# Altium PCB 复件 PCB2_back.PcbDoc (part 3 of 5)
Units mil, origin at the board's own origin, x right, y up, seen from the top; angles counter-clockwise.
Board outline 6299 x 3937 mil, 4 copper layers (TopLayer, GROUND, VCC, BottomLayer); 290 components, 470 nets, 2252 pads, 827 vias.
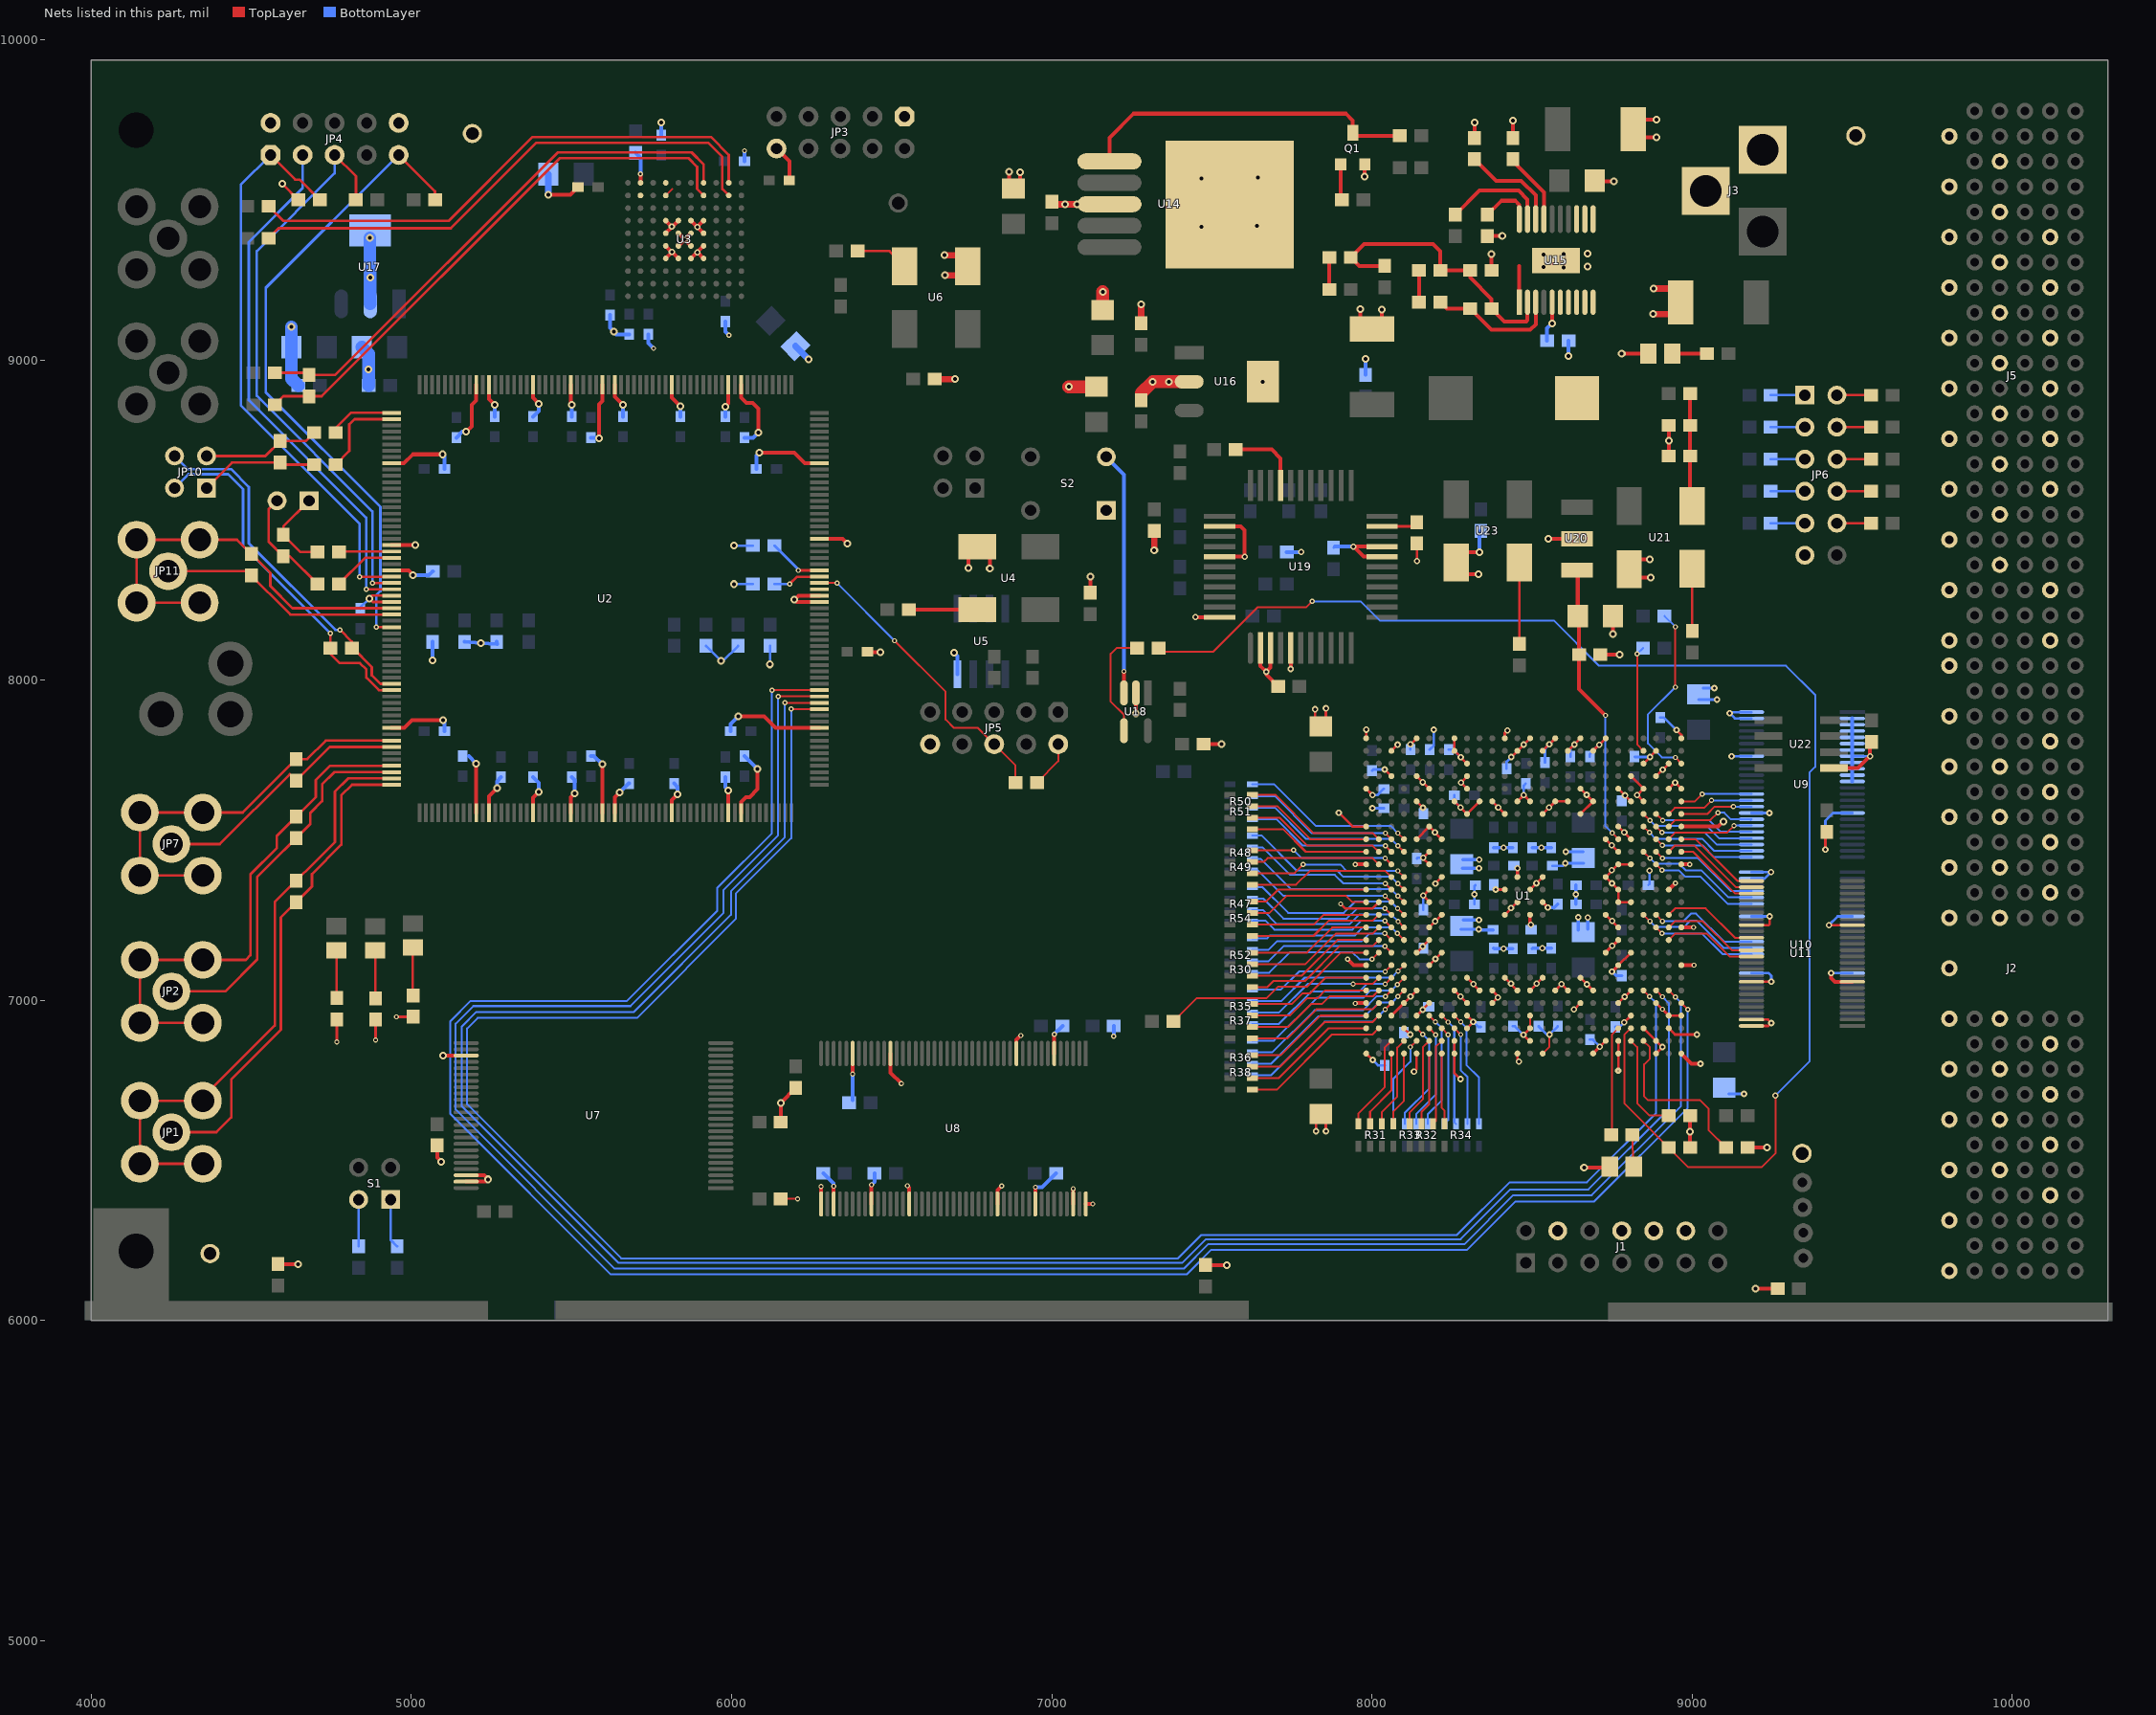
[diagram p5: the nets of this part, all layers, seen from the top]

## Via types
v1: diameter 16, hole 8, TopLayer to BottomLayer, 408 vias
v2: diameter 20, hole 10, TopLayer to BottomLayer, 220 vias
v3: diameter 24, hole 12, TopLayer to BottomLayer, 196 vias
v4: diameter 56.69, hole 56.69, TopLayer to BottomLayer, 2 vias
v5: diameter 20, hole 0, TopLayer to BottomLayer, 1 vias

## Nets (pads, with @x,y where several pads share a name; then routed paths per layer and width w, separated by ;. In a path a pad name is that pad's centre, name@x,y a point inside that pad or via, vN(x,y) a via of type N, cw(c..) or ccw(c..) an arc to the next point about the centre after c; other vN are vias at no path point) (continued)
GND: C5.1 C6.1 C7.1 C8.1 C9.1 C10.1 C11.1 C14.2 C15.2 C16.1 C17.1 C18.1 C19.1 C20.1 C21.1 C22.1 C23.1 C24.1 C25.1 C26.1 C27.2 C37.2 C38.2 C39.2 C40.2 C41.2 C42.2 C43.2 C44.2 C45.2 C46.2 C47.2 C48.2 C49.2 C50.2 C51.2 C52.2 C53.2 C54.1 C55.2 C56.2 C57.2 C58.2 C59.2 C60.2 C63.1 C64.1 C65.2 C66.2 C67.2 C68.2 C69.2 C70.2 C71.2 C72.2 C73.2 C74.2 C75.2 C76.2 C77.2 C78.1 C79.2 C80.2 C81.2 C82.2 C83.2 C84.2 C85.2 C86.2 C87.2 C90.1 C95.1 C96.1 C97.2 C98.2 C99.2 C100.2 C101.2 C103.2 C104.2 C105.2 C106.2 C107.2 C108.2 C109.2 C110.2 C111.2 C112.2 C114.2 C115.2 C116.2 C117.2 C119.2 C120.2 C121.2 C123.2 C124.2 C125.1 C126.1 C127.1 C128.1 C129.1 C130.1 C131.1 C132.1 C133.1 C134.2 C135.2 C136.2 C137.2 C138.2 C139.2 C140.2 C141.2 C142.2 C143.2 C144.2 C145.2 C146.2 C147.2 C148.2 C149.2 C150.2 C151.2 C152.2 C154.1 C156.1 C158.1 C160.1 C161.1 C162.1 C163.1 C164.2 C165.1 C166.1 DS6.2 DS9.2 FB5.2 FB6.2 FB7.2 FB8.2 J1.4 J1.8 J1.10 J1.12 J2.B4 J2.B6 J2.B8 J2.B10 J2.B16 J2.B18 J2.B20 J2.B22 J2.D5 J2.D7 J2.D9 J2.D11 J2.D15 J2.D17 J2.D19 J2.D21 J2.F1 J2.F3 J2.F5 J2.F7 J2.F9 J2.F11 J2.F13 J2.F15 J2.F17 J2.F19 J2.F21 J2.F23 J2.F25 J3.2 J3.3 J5.B1 J5.B3 J5.B7 J5.B9 J5.B11 J5.B13 J5.B15 J5.B17 J5.D4 J5.D6 J5.D8 J5.D10 J5.D12 J5.D14 J5.D16 J5.D18 J5.D20 J5.F1 J5.F3 J5.F5 J5.F7 J5.F9 J5.F11 J5.F13 J5.F15 J5.F17 J5.F19 J5.F21 JP3.1 JP3.10 JP4.2 JP4.10 JP5.2 JP5.10 JP6.11 pad.5 pad.6 pad.7 pad.8 Q1.3 R15.2 R17.1 R18.2 R19.2 R22.1 R23.1 R28.1 R39.2 R59.1 R65.1 R67.1 R79.1 R83.1 R84.1 S2.1 U1.A1 U1.A3 U1.A6 U1.A8 U1.A12 U1.A14 U1.A19 U1.A22 U1.A26 U1.AA4 U1.AA5 U1.AA8 U1.AA10 U1.AA11 U1.AA13 U1.AA14 U1.AA16 U1.AA17 U1.AA19 U1.AA22 U1.AB1 U1.AB2 U1.AB4 U1.AB6 U1.AB9 U1.AB18 U1.AB21 U1.AB26 U1.AC3 U1.AC5 U1.AC18 U1.AC22 U1.AC24 U1.AD2 U1.AD4 U1.AD18 U1.AE3 U1.AE8 U1.AE10 U1.AE12 U1.AE14 U1.AE19 U1.AE24 U1.AF1 U1.AF7 U1.AF9 U1.AF11 U1.AF13 U1.AF15 U1.AF19 U1.AF22 U1.AF26 U1.B3 U1.B6 U1.B7 U1.B13 U1.B19 U1.C2 U1.C4 U1.C13 U1.C18 U1.C23 U1.D1 U1.D2 U1.D5 U1.D13 U1.D18 U1.D22 U1.D24 U1.E3 U1.E6 U1.E9 U1.E16 U1.E18 U1.E21 U1.E23 U1.E26 U1.F5 U1.F8 U1.F10 U1.F11 U1.F13 U1.F14 U1.F16 U1.F17 U1.F19 U1.F22 U1.G9 U1.G12 U1.G15 U1.G18 U1.H1 U1.H6 U1.H21 U1.H26 U1.J5 U1.J7 U1.J20 U1.J22 U1.K6 U1.K21 U1.L1 U1.L6 U1.L21 U1.M7 U1.M13 U1.M15 U1.M20 U1.N5 U1.N6 U1.N12 U1.N14 U1.N21 U1.N25 U1.P2 U1.P6 U1.P13 U1.P15 U1.P21 U1.R7 U1.R12 U1.R14 U1.R20 U1.T1 U1.T5 U1.T6 U1.T21 U1.T26 U1.U6 U1.U21 U1.V5 U1.V7 U1.V20 U1.V22 U1.W1 U1.W6 U1.W21 U1.W26 U1.Y9 U1.Y12 U1.Y15 U1.Y18 U2.10 U2.30 U2.31 U2.40 U2.52 U2.69 U2.71 U2.80 U2.89 U2.91 U2.96 U2.102 U2.109 U2.111 U2.129 U2.142 U2.150 U2.151 U2.171 U2.190 U2.192 U2.199 U2.205 U2.210 U2.212 U2.221 U2.230 U2.232 U3.D4 U3.D5 U3.D6 U3.D7 U3.E4 U3.E5 U3.E6 U3.E7 U3.F4 U3.F5 U3.F6 U3.F7 U3.G4 U3.G5 U3.G6 U3.G7 U4.2 U5.4 U6.2 U7.27 U7.46 U7.47 U8.6 U8.12 U8.32 U8.38 U8.44 U8.46 U8.52 U8.58 U8.72 U8.78 U8.84 U8.86 U9.2 U9.3 U9.4 U9.5 U9.6 U9.7 U9.8 U9.9 U9.10 U9.11 U9.12 U9.17 U9.32 U9.41 U9.47 U9.48 U10.8 U10.17 U10.32 U10.41 U10.47 U10.48 U11.8 U11.17 U11.32 U11.41 U11.47 U11.48 U14.3 U15.1 U15.11 U15.12 U15.13 U16.2 U16.4 U17.2 U17.4 U18.2 U19.2 U19.3 U19.5 U19.18 U19.19 U19.35 U19.38 U19.44 U20.2 U21.2 U22.5 U23.2 | length 21482.2
  TopLayer w6: R59.1@6153.46,6380 v1(6206,6380) ; R28.1@6953.46,7680 7020,7746.54 JP5.2@7020,7800 ; U1.C13@8493.56,6912.74 U1.D13@8493.56,6952.11 ; U1.A12@8532.93,6834 8553.99,6855.06 v2(8553.99,6893)
  TopLayer w8: v3(4596.54,9550) R17.1@4646.54,9500 ; v1(4767,6870) R19.2@4767,6940.54 ; v1(4888,6876) R18.2@4888,6939.54 ; U2.151@4937.69,8244.16 4878.84,8244.16 v3(4868,8255) 4876.84,8263.84 U2.150@4937.69,8263.84 ; v1(4952.54,6948.54) R15.2@5005,6948.54 ; C147.2@7822,7855 v2(7822,7909) ; v2(7825,6591) C150.2@7825,6639 ; v2(7856,6591) C150.2@7856,6644 ; C147.2@7856,7851 v2(7856,7912) ; v2(7896,7586) 7939.34,7542.66 U1.W26@7981.75,7542.66 ; v1(7902,7301) 7916,7287 8001.68,7287 U1.N25@8021.12,7306.44 ; U1.A26@7981.75,6834 v2(8002,6813.75) ; U1.AB26@7981.75,7660.77 v2(8001.52,7641) ; U1.AF26@7981.75,7818.25 v2(7981.75,7845.25) ; v2(8039.63,7721) U1.AC24@8060.49,7700.14 ; U1.D24@8060.49,6952.11 U1.F22@8139.23,7030.85 ; U1.AE24@8060.49,7778.88 v2(8080,7798.39) ; U1.C23@8099.86,6912.74 v2(8119.6,6893) ; v2(8120,7799.02) U1.AF22@8139.23,7818.25 ; v2(8131,6777) 8139.23,6785.23 U1.A22@8139.23,6834 ; U1.D22@8139.23,6952.11 U1.E21@8178.6,6991.48 ; U1.J22@8139.23,7148.96 U1.K21@8178.6,7188.33 ; U1.V22@8139.23,7503.29 U1.W21@8178.6,7542.66 U1.V20@8217.97,7503.29 ; U1.AA22@8139.23,7621.4 v2(8159,7601.63) ; U1.AC22@8139.23,7700.14 U1.AB21@8178.6,7660.77 ; v2(8140,8372) R39.2@8140,8426.54 ; U1.H21@8178.6,7109.59 U1.J20@8217.97,7148.96 ; U1.L21@8178.6,7227.7 U1.M20@8217.97,7267.07 ; U1.N21@8178.6,7306.44 8178.6,7308.4 v2(8160,7327) 8178.6,7345.6 U1.P21@8178.6,7345.81 ; U1.T21@8178.6,7424.55 8159.68,7443.47 v2(8159.68,7445) U1.U21@8178.6,7463.92 ; v2(8197.79,7365) U1.R20@8217.97,7385.18 ; U1.B19@8257.34,6873.37 8257.34,6772.66 v2(8276,6754) ; U1.F19@8257.34,7030.85 U1.E18@8296.71,6991.48 ; U1.AA19@8257.34,7621.4 U1.Y18@8296.71,7582.03 U1.AA17@8336.08,7621.4 ; U1.AF19@8257.34,7818.25 U1.AE19@8257.34,7778.88 U1.AD18@8296.71,7739.51 ; U1.C18@8296.71,6912.74 8316,6932.03 v2(8316,6932.82) U1.D18@8296.71,6952.11 ; U1.G18@8296.71,7070.22 U1.F17@8336.08,7030.85 ; U1.AB18@8296.71,7660.77 8278,7679.48 v2(8278,7680) 8296.71,7698.71 U1.AC18@8296.71,7700.14 ; U1.E16@8375.45,6991.48 v2(8393,7009.03) 8393,7013.3 U1.F16@8375.45,7030.85 ; U1.AA16@8375.45,7621.4 U1.Y15@8414.82,7582.03 ; U1.G15@8414.82,7070.22 U1.F14@8454.19,7030.85 ; U1.M15@8414.82,7267.07 U1.N14@8454.19,7306.44 ; U1.AF15@8414.82,7818.25 8414.82,7834.82 v2(8423,7843) ; v2(8435,7759.69) v2(8473.88,7798.58) U1.AF13@8493.56,7818.25 ; U1.A14@8454.19,6834 8454.19,6813.81 v2(8459,6809) ; U1.AA14@8454.19,7621.4 v2(8473.79,7641) 8473.96,7641 U1.AA13@8493.56,7621.4 ; U1.B13@8493.56,6873.37 8491.45,6873.37 v2(8472.82,6892) U1.C13@8493.56,6912.74 ; U1.F13@8493.56,7030.85 U1.G12@8532.93,7070.22 ; U1.P13@8493.56,7345.81 U1.R12@8532.93,7385.18 ; U1.Y12@8532.93,7582.03 U1.AA11@8572.3,7621.4 U1.AA10@8611.67,7621.4 ; U1.AE12@8532.93,7778.88 U1.AF11@8572.3,7818.25 ; U1.F11@8572.3,7030.85 8591.52,7050.07 v2(8591.52,7051) U1.F10@8611.67,7030.85 ; U1.AE10@8611.67,7778.88 U1.AF9@8651.04,7818.25 ; v2(8631,6971.44) U1.E9@8651.04,6991.48 ; U1.G9@8651.04,7070.22 U1.F8@8690.41,7030.85 ; U1.Y9@8651.04,7582.03 U1.AA8@8690.41,7621.4 U1.AB9@8651.04,7660.77 ; U1.A8@8690.41,6834 U1.B7@8729.78,6873.37 ; U1.AE8@8690.41,7778.88 U1.AF7@8729.78,7818.25 ; U1.M7@8729.78,7267.07 U1.L6@8769.15,7227.7 ; U1.V7@8729.78,7503.29 U1.U6@8769.15,7463.92 ; v5(8769,6780) 8769.15,6780.15 U1.B6@8769.15,6873.37 ; U1.E6@8769.15,6991.48 U1.F5@8808.52,7030.85 ; U1.H6@8769.15,7109.59 U1.J5@8808.52,7148.96 ; U1.W6@8769.15,7542.66 U1.V5@8808.52,7503.29 ; U1.AB6@8769.15,7660.77 U1.AA5@8808.52,7621.4 ; v2(8787.41,6931) U1.D5@8808.52,6952.11 ; U1.N5@8808.52,7306.44 U1.N6@8769.15,7306.44 U1.P6@8769.15,7345.81 U1.R7@8729.78,7385.18 U1.T6@8769.15,7424.55 U1.T5@8808.52,7424.55 ; U1.AC5@8808.52,7700.14 U1.AB4@8847.89,7660.77 v2(8828.12,7641) 8828,7641 8847.6,7621.4 U1.AA4@8847.89,7621.4 ; U1.C4@8847.89,6912.74 8906.63,6854 v2(8907.26,6854) U1.A3@8887.26,6834 ; U1.AD4@8847.89,7739.51 U1.AE3@8887.26,7778.88 ; U1.E3@8887.26,6991.48 U1.D2@8926.63,6952.11 U1.D1@8966,6952.11 ; U1.AC3@8887.26,7700.14 U1.AD2@8926.63,7739.51 ; U1.C2@8926.63,6912.74 8946.37,6893 v2(9015,6893) ; U1.AB2@8926.63,7660.77 8945.86,7680 v2(8946.77,7680) U1.AB1@8966,7660.77 ; v2(8951,7844) 8966,7829 U1.AF1@8966,7818.25 ; U11.48@9185.04,6920 9238,6920 v2(9247,6929) 9236.32,6939.69 U11.47@9185.04,6939.69 ; U11.41@9185.04,7057.8 v2(9247.2,7057.8) ; U11.32@9185.04,7234.96 9238.96,7234.96 9242.2,7238.2 v2(9242.2,7262.2) ; v2(9416,7471) 9416,7522.54 C166.1@9420,7526.54 ; v2(9427.04,7234.96) U11.17@9500,7234.96
  TopLayer w10: v2(8386.19,7345.81) U1.P15@8414.82,7345.81 ; U1.R14@8454.19,7385.18 v2(8454.19,7412.19) ; U1.M13@8493.56,7267.07 8493.56,7238.44 v2(8496,7236) ; U1.N12@8532.93,7306.44 v2(8549.37,7290) ; U1.J7@8729.78,7148.96 U1.K6@8769.15,7188.33 ; v2(8749.56,7090) U1.H6@8769.15,7109.59
  TopLayer w12: FB8.2@4583,6176.46 v3(4645.46,6176.46) ; U2.171@4937.69,7850.46 4977.46,7850.46 5002,7875 v3(5099,7875) ; U2.142@4937.69,8421.32 v3(5012.32,8421.32) ; U2.129@4937.69,8677.23 4976.23,8677.23 5004,8705 v3(5097,8705) ; C19.1@5080,6546.54 5080,6509 v3(5093,6496) ; v3(5098,6827) U7.27@5170.72,6827.39 ; U7.47@5170.72,6433.69 5231.69,6433.69 v3(5239,6441) 5226.63,6453.37 U7.46@5170.72,6453.37 ; v3(5171,8776) 5188,8793 5188,8859 5202.46,8873.46 U2.111@5202.46,8922.31 ; U2.190@5202.46,7585.69 v3(5202.46,7739.54) ; U2.192@5241.83,7585.69 5241.83,7637.83 v3(5267,7663) ; U2.109@5241.83,8922.31 5241.83,8877.17 v3(5260,8859) ; U2.199@5379.62,7585.69 5379.62,7632.62 v3(5398,7651) ; U2.102@5379.62,8922.31 5379.62,8881.38 v3@5398,8863 ; v3(5427.2,9516.2) 5496.2,9516.2 C9.1@5520,9540 ; U2.205@5497.73,7585.69 5497.73,7634.73 v3(5509,7646) ; U2.96@5497.73,8922.31 5497.73,8862.27 v3(5500,8860) ; v3(5586,8755) 5586,8861 5596.16,8871.16 U2.91@5596.16,8922.31 ; U2.210@5596.16,7585.69 v3(5596.16,7736.84) ; U2.212@5635.53,7585.69 5635.53,7634.53 v3(5650,7649) ; U2.89@5635.53,8922.31 5635.53,8884.47 v3(5660,8860) ; U3.G4@5794.11,9316.78 5813.73,9336.4 v2@5813.73,9336.53 ; U3.F4@5794.11,9356.15 U3.G5@5833.48,9316.78 ; U3.E4@5794.11,9395.52 5813.8,9415.2 U3.D5@5833.48,9434.89 ; U3.D4@5794.11,9434.89 v2(5813.05,9415.95) ; U2.221@5812.69,7585.69 5812.69,7624.69 v3(5831,7643) ; U2.80@5812.69,8922.31 5812.69,8882.31 v3(5840,8855) ; U3.F5@5833.48,9356.15 U3.E6@5872.85,9395.52 ; U3.E5@5833.48,9395.52 v2(5853.17,9375.83) U3.F6@5872.85,9356.15 ; U3.G6@5872.85,9316.78 v2@5892.05,9335.98 ; U3.D6@5872.85,9434.89 U3.E7@5912.22,9395.52 ; v2(5892.47,9415.27) 5892.6,9415.27 U3.D7@5912.22,9434.89 ; U3.G7@5912.22,9316.78 v2(5893.02,9335.98) v2@5892.05,9335.98 ; U3.F7@5912.22,9356.15 v2@5892.05,9335.98 ; v3(5980,8854) 5989.86,8863.86 U2.71@5989.86,8922.31 ; U2.230@5989.86,7585.69 v3(5989.86,7655.14) ; v3(6021,7887) 6101,7887 6137.54,7850.46 U2.10@6274.31,7850.46 ; U2.232@6029.23,7585.69 6029.23,7619.23 6045,7635 6057,7635 6081,7659 v3(6081,7721.99) ; U2.69@6029.23,8922.31 6029.23,8882.77 6046,8866 6065,8866 6083,8848 v3(6083,8773) ; v3(6086,8710) 6196,8710 6228.77,8677.23 U2.52@6274.31,8677.23 ; JP3.10@6140,9660 6180,9620 C7.1@6180,9560 ; C27.2@6153.46,6620 v3(6153.46,6680) C20.1@6200,6726.54 ; U2.30@6274.31,8244.16 6202.84,8244.16 v3(6196,8251) 6208.84,8263.84 U2.31@6274.31,8263.84 ; U2.40@6274.31,8441.01 6345.99,8441.01 v3(6361,8426) ; U8.44@6279.23,6364 v1(6279.23,6418.23) ; U8.46@6318.6,6364 v1(6318.6,6419.4) ; v1(6377.65,6769.35) U8.38@6377.65,6834 ; C104.2@6422,8087.01 v3(6463.99,8087.01) ; U8.52@6436.71,6364 v1(6436.71,6423.71) ; U8.32@6495.77,6834 6495.77,6774.23 v1(6530,6740) ; v1(6549,6421) 6554.82,6415.18 U8.58@6554.82,6364 ; v3(6740,8350) U4.2@6740,8416 ; v3(6806,8348) U4.2@6806,8409 ; U8.72@6830.41,6364 6830.41,6407.41 v1(6843,6420) ; C135.2@6866,9536 v3(6866,9587) ; U8.12@6889.47,6834 6889.47,6876.47 v1(6903,6890) ; C135.2@6901,9531 v3(6901,9586) ; U8.78@6948.52,6364 v1(6948.52,6416.52) ; U8.6@7007.57,6834 v1(7007.57,6894.11) ; U8.84@7066.63,6364 v1(7066.63,6411.63) ; U8.86@7106,6364 v1(7128,6364) ; C17.1@7120,8273.46 v3(7120,8323) ; v3(7262.6,7895.4) U18.2@7262.6,7960 ; v2(7448.54,8196.46) U19.44@7523.54,8196.46 ; C133.1@7473.46,7800 v3(7530,7800) ; FB7.2@7480,6173.46 v3(7546.46,6173.46) ; U19.38@7523.54,8385.43 v2(7602.43,8385.43) 7602.43,8467.57 7590.08,8479.92 U19.35@7523.54,8479.92 ; U19.2@7651.5,8100 7651.5,8044.5 v2(7670,8026) ; U19.3@7682.99,8100 7682.99,8038.99 v2(7670,8026) ; C156.1@7706.54,7980 7670,8016.54 v2(7670,8026) ; v2(7745.98,8034.98) U19.5@7745.98,8100 ; v1(7924,7128) 7942.41,7109.59 U1.H26@7981.75,7109.59 ; v1(7947.45,7424.55) U1.T26@7981.75,7424.55 ; v1(7948,6990) 7949.48,6991.48 U1.E26@7981.75,6991.48 ; C138.2@7964,9097 v3(7964,9159) ; v3(7977.4,9572.6) Q1.3@7977.4,9610.79 ; C138.2@8031,9101 v3(8031,9157) ; U19.18@8031.42,8385.43 7973.43,8385.43 v2(7941.93,8416.93) U19.19@8031.42,8416.93 ; U23.2@8255,8331 v3(8333,8331) ; U23.2@8259,8400 v3(8335,8400) ; C54.1@8320,9693.46 v3(8320,9742) ; R65.1@8360,9386.54 v3(8406.46,9386.54) ; R67.1@8373.46,9280 v3(8373.46,9330.46) ; C64.1@8440,9693.46 v3(8440,9747) ; U15.1@8460,9180 8460,9293 ; v3(8550.57,8441.57) U20.2@8640,8441.57 ; v3(8662,6477) DS9.2@8743.6,6478 ; C146.2@8695,9557 v3(8756,9557) ; C163.1@8713.46,8080 v3(8774,8080) ; v3(8752.8,8143.2) C164.2@8752.8,8200 ; v3(8780,9020) DS6.2@8862.6,9020 ; U21.2@8802,8320 v3(8870,8320) ; U21.2@8813,8377 v3(8868,8377) ; C134.2@8819,9695 v3(8889,9695) ; C134.2@8819,9751 v3(8889,9751) ; C161.1@8926.54,8695 C160.1@8926.54,8795 ; U1.P2@8926.63,7345.81 v1(8947,7366) ; U1.A1@8966,6834 8998,6802 v2(9026,6802) ; U1.H1@8966,7109.59 v1(9005.59,7109.59) ; U1.L1@8966,7227.7 v1(9004.3,7227.7) ; U1.T1@8966,7424.55 v1(8992.55,7424.55) ; U1.W1@8966,7542.66 9081.66,7542.66 v3(9097,7558) ; R83.1@8993.46,6540 R84.1@8993.46,6640 ; R79.1@9173.46,6540 v3(9234,6540) ; v3(9198,6100) FB6.2@9266.54,6100 ; v2(9434.04,7085.04) 9434.04,7069.76 9446,7057.8 U11.8@9500,7057.8 ; U22.5@9442.36,7725 9518,7725 v2(9555.2,7762.2) 9555.2,7801.74 C162.1@9560,7806.54
  TopLayer w20: C18.1@6633.46,8940 v3(6698,8940) ; v3(6665,9327) U6.2@6726,9327 ; v3(6666,9264) U6.2@6732,9264 ; C95.1@7000,9493.46 7007.46,9486 U14.3@7180,9486 ; C96.1@7279,9114.46 v3(7279,9173) ; v3(7320,8405) FB5.2@7320,8466.54 ; v3(8878,9143) C140.2@8956,9143 ; v3(8880,9223) C140.2@8962,9223
  TopLayer w40: v3(7052.88,8916.12) C137.2@7139,8916.12 ; C136.2@7159,9156.12 v3(7159,9213) ; C125.1@7279,8874.46 7279,8896 v3(7315,8932) U16.2@7429,8932
  BottomLayer w6: C47.2@8862.99,7360 C47.2@8867,7364.01
  BottomLayer w8: C108.2@4840,8222.99 4840,8227 v3(4868,8255) ; C128.1@5920,8106.54 v3(5966.54,8060) 5973.46,8060 C141.2@6020,8106.54 ; v3(6007,8300) R22.1@6066.54,8300 ; v3(6007,8420) R23.1@6066.54,8420 ; v3(6120,8049) C130.1@6120,8106.54 ; C154.1@7880,8413.46 C154.1@7883.46,8416.93 ; C49.2@8000,7717.01 8003.99,7721 v2(8039.63,7721) ; v2(8001,7600) C57.2@8037.01,7600 ; v2(8001.52,7641) 8017.09,7641 C65.2@8036.87,7660.77 ; v2(8002,6813.75) 8018.74,6797.01 C75.2@8040,6797.01 ; C58.2@8120,7782.99 v2(8120,7799.02) ; C67.2@8140,7442.99 8142.01,7445 v2(8159.68,7445) ; C68.2@8160,7282.99 v2(8160,7327) ; C40.2@8180,7782.99 8193,7795.99 v2(8193,7845) ; C56.2@8240,7782.99 8253.01,7782.99 v2(8277,7759) ; C59.2@8257.01,7640 8257.01,7621.73 v2(8276.34,7602.4) ; v2(8316,6932.82) 8331.81,6917.01 C76.2@8340,6917.01 ; C63.1@8320,7300 8320,7357.01 C71.2@8322.99,7360 ; C48.2@8420,7722.99 8420,7744.69 v2(8435,7759.69) ; C83.2@8440,6919.01 8445.81,6919.01 v2(8472.82,6892) ; v2(8473.79,7641) 8473.79,7670.79 C37.2@8480,7677.01 ; C77.2@8520.99,6919.01 C77.2@8520,6919.01 8546.01,6893 v2(8553.99,6893) C82.2@8580,6919.01 ; C46.2@8540,7742.99 8540,7785.95 v2(8553.41,7799.37) ; C52.2@8562.99,7420 8596,7420 v2(8604,7428) ; C39.2@8620,7760.99 8620,7787.21 v2(8631.67,7798.88) ; C86.2@8680,6877.01 8689.83,6877.01 v2(8711.62,6855.21) ; C38.2@8680,7760.99 8680,7768.47 v2(8709.82,7798.29) ; C85.2@8760,6917.01 8773.42,6917.01 v2(8787.41,6931) ; C41.2@8820,7760.99 8820.99,7760 v2(8868,7760) ; C47.2@8867,7364.01 v2(8867,7405) ; C45.2@8900,7882.99 8912.01,7882.99 v2(8951,7844) ; C144.2@9020,7939 v2(9077,7939) ; C144.2@9034,7975 v2(9069,7975) ; C152.2@9114,6708 v2(9162,6708) ; v2(9122.8,7762.2) U9.41@9185.04,7762.2 ; U10.32@9185.04,7085.04 9238.96,7085.04 9247.2,7076.8 v2(9247.2,7057.8) ; U10.41@9185.04,7262.2 v2(9242.2,7262.2) ; U10.47@9185.04,7380.31 9226.32,7380.31 v2(9246,7400) U10.48@9185.04,7400 ; U9.32@9185.04,7585.04 v2(9240.96,7585.04) ; U9.47@9185.04,7880.31 9133.68,7880.31 v2(9117,7897) 9120,7900 U9.48@9185.04,7900 ; v2(9416,7471) 9416,7561 9440.04,7585.04 U9.17@9500,7585.04 ; v2(9427.04,7234.96) 9454.28,7262.2 U10.8@9500,7262.2 ; v2(9434.04,7085.04) U10.17@9500,7085.04 ; U9.8@9500,7762.2 v2(9555.2,7762.2)
  BottomLayer w10: C149.2@8277,7222 v2(8333,7222) 8335,7220 C78.1@8378,7220 ; C148.2@8282,7412 v2(8334,7412) ; C148.2@8284,7439 v2(8335,7439) ; C149.2@8285,7251 v2(8334,7251) ; C79.2@8380,7162.99 8382,7160.99 C80.2@8440,7160.99 ; C53.2@8380,7477.01 C42.2@8440,7477.01 ; C81.2@8500,7160.99 8502,7162.99 C87.2@8560,7162.99 ; C43.2@8500,7477.01 C51.2@8560,7477.01 ; v2(8549.37,7290) 8570,7290 C90.1@8580,7300 ; v2(8604,7428) C145.2@8660,7428 ; v2(8605,7464) C145.2@8659,7464 ; C50.2@8637.01,7300 C44.2@8637.01,7360 ; C151.2@8644,7220 v2(8644,7259) ; C151.2@8674,7222 v2(8674,7258) ; v2(8749.56,7090) 8762.55,7077.01 C84.2@8780,7077.01
  BottomLayer w12: v3(5066,8061) C131.1@5066,8119.54 ; v3(5097,8705) 5102.99,8699.01 C103.2@5102.99,8660 ; v3(5099,7875) 5102.99,7871.01 C97.2@5102.99,7840 ; C110.2@5140,8757.01 5158.99,8776 v3(5171,8776) ; C129.1@5166,8119.54 v3(5217,8116) 5267,8112 C142.2@5266,8119.54 ; 5179.01,7762.99 v3(5202.46,7739.54) ; C124.2@5260,8822.99 v3(5260,8859) ; v3(5267,7663) 5267,7684.01 C100.2@5280,7697.01 ; C106.2@5380,7697.01 5398,7679.01 v3(5398,7651) ; C112.2@5380,8822.99 5397,8839.99 v3(5397,8862) ; C111.2@5500,7697.01 5509,7688.01 v3(5509,7646) ; C101.2@5500,8822.99 v3(5500,8860) ; C109.2@5560,7762.99 5570.01,7762.99 v3(5596.16,7736.84) ; C114.2@5560,8757.01 5583.99,8757.01 v3(5586,8755) ; C10.1@5620,9140 5620,9100 5640,9080 C6.1@5680,9080 ; v3(5650,7649) 5678.01,7677.01 C116.2@5680,7677.01 ; C121.2@5660,8822.99 v3(5660,8860) ; C5.1@5740,9080 5740,9052 v1(5756,9036) ; C11.1@5780,9702 v3(5780,9742) ; C123.2@5820,7677.01 5831,7666.01 v3(5831,7643) ; C117.2@5840,8822.99 v3(5840,8855) ; C120.2@5980,7697.01 5980,7665 v3(5989.86,7655.14) ; C107.2@5980,8822.99 v3(5980,8854) ; C16.1@5980,9120 5980,9089 v1(5992,9077) ; C119.2@5997.01,7840 5997.01,7863.01 v3(6021,7887) ; C105.2@6040,7762.99 v3(6081,7721.99) ; C99.2@6040,8757.01 6067.01,8757.01 v3(6083,8773) ; C8.1@6040,9620 v1(6040,9653) ; C115.2@6077.01,8660 6077.01,8701.01 v3(6086,8710) ; C24.1@6286.54,6460 6318.6,6427.94 v1(6318.6,6419.4) ; C21.1@6377.65,6688.88 v1(6377.65,6769.35) ; v1(6436.71,6423.71) 6446.54,6433.54 C25.1@6446.54,6460 ; v3(6695,8085) 6705,8075 U5.4@6705,8017.64 ; v1(6948.52,6416.52) 6969.98,6416.52 C26.1@7013.46,6460 ; v1(7007.57,6894.11) C23.1@7033.46,6920 ; v1(7193.46,6887.46) C22.1@7193.46,6920 ; C158.1@7733.46,8400 v2(7779,8400) ; C154.1@7883.46,8416.93 v2(7941.93,8416.93) ; C126.1@7980,8953.46 v3(7980,9003) ; v3(8335,8400) 8335,8461.54 C165.1@8340,8466.54 ; U9.12@9500,7683.47 U9.2@9500,7880.31
  BottomLayer w20: v3@4866.54,8969.46 v3@4866.54,8970 ; v3(5427.2,9516.2) C14.2@5427.2,9580 ; C15.2@6198.97,9043.34 v3(6240.31,9002)
  BottomLayer w40: v3(4624.88,9102.88) 4624.88,8941.65 C132.1@4646.54,8920 ; C139.2@4844.88,9040 4866,9018.88 v3(4866,8970) 4866.54,8969.46 C127.1@4866.54,8920 ; v3(4870,9381) U17.2@4871,9175
  other v1: 8906.68,6972.06
  other v2: 8158.11,6970.99 8789,7011 8120.43,7012.05 8276.51,7011.68 8316.5,7050.42 8671,7050 8434,7052 8514,7052 8198.14,7129.13 8411,7160.99 8532,7162.99 8158.45,7168.18 8750,7170 8197,7247 8750,7248 8434,7288 8320,7331 8637.01,7331 8749.46,7365.5 8513.29,7365.54 8749,7406 8411,7477.01 8529,7477.01 8748.71,7484.36 8788,7524 8196.61,7524.65 8394,7602 8553.21,7602.31 8790,7640 8670.04,7641.77 8158.49,7680.88 8907.77,7720.65 5813.2,9337.06
  other v3: 8993.47,6590 8926.54,8747 7366,8932 7659,8932 5632,9088 4871,9257 8599,9288 8536,9290 8673,9292 8535,9329 8599,9330 8673,9332 7467,9415 7641,9419 7042,9486 7078,9486 7467,9567 7643,9569
GP02: R86.1 U1.C6 | length 342.1
  TopLayer w6: R86.1@8746.54,6580 8749,6582.46 8749,6892.59 U1.C6@8769.15,6912.74
GP04: U1.F4 U2.13 | length 6532.5
  TopLayer w6: v1(6186,7909.51) U2.13@6274.31,7909.51 ; U1.F4@8847.89,7030.85 v1(8867,7011.74)
  BottomLayer w6: v1(6186,7909.51) 6186,7506 6013,7333 6013,7254 5704,6945 5207,6945 5174,6912 5174,6675 5655,6194 7394,6194 7467,6267 8265,6267 8430,6432 8671,6432 8887,6648 8887,6991.74 v1(8867,7011.74)
GP05: U1.F3 U2.14 | length 6632.8
  TopLayer w6: v1(6166,7929.2) U2.14@6274.31,7929.2 ; U1.F3@8887.26,7030.85 v1(8907,7011.11)
  BottomLayer w6: v1(6166,7929.2) 6166,7509 5998,7341 5998,7267 5695,6964 5203,6964 5157,6918 5157,6670 5647,6180 7407,6180 7481,6254 8277,6254 8432,6409 8676,6409 8927,6660 8927,6991.11 v1(8907,7011.11)
GP06: U1.F2 U2.15 | length 6744
  TopLayer w6: v1(6145,7948.88) U2.15@6274.31,7948.88 ; U1.F2@8926.63,7030.85 v1(8947,7010.48)
  BottomLayer w6: v1(6145,7948.88) 6145,7515 5974,7344 5974,7272 5684,6982 5193,6982 5138,6927 5138,6659 5635,6162 7412,6162 7488,6238 8288,6238 8441.27,6391.27 8686.27,6391.27 8965,6670 8965,6992.48 v1(8947,7010.48)
GP07: U1.E1 U2.16 | length 6797.1
  TopLayer w6: v1(6126,7968.57) U2.16@6274.31,7968.57 ; U1.E1@8966,6991.48 v1(8986,6971.48)
  BottomLayer w6: v1(6126,7968.57) 6126,7522 5955,7351 5955,7280 5673,6998 5185,6998 5121,6934 5121,6646 5623,6144 7421,6144 7497,6220 8296,6220 8448.02,6372.02 8694.02,6372.02 8986,6664 v1(8986,6971.48)
IN1+: C2.1 R11.1 U3.A7 | length 1702.3
  TopLayer w8: C2.1@4573.46,8960 4673.46,8960 R11.1@4680,8953.46 4762.13,8953.46 5456.67,9648 5875,9648 5912.22,9610.78 U3.A7@5912.22,9553
IN1-: C1.1 R11.2 U3.B7 | length 1746.4
  TopLayer w8: C1.1@4573.46,8860 4600,8886.54 4719.54,8886.54 5463,9630 5865,9630 5892,9603 5892,9533.85 U3.B7@5912.22,9513.63
IN2+: R8.1 U3.A2 | length 99.9
  TopLayer w12: U3.A2@5715.37,9553 v1(5715.37,9580.37)
  BottomLayer w12: R8.1@5700,9646.54 5715.37,9631.17 v1(5715.37,9580.37)
IN2-: U3.B2
JTAG_TCK: JP4.1 R17.2 U2.147 | length 1820.4
  TopLayer w8: JP4.1@4560,9640 4637,9563 4650.46,9563 R17.2@4713.46,9500 ; v1(4838.1,8322.9) U2.147@4937.69,8322.9
  BottomLayer w8: JP4.1@4560,9640 4467,9547 4467,8858 4838.1,8486.9 v1(4838.1,8322.9)
JTAG_TDI: JP4.9 R14.1 U2.155 | length 2034.8
  TopLayer w8: v1(4890,8165.42) U2.155@4937.69,8165.42 ; JP4.9@4960,9640 5073.46,9526.54 R14.1@5073.46,9500
  BottomLayer w8: v1(4890,8165.42) 4890,8265 4903,8278 4903,8541 4545,8899 4545,9225 JP4.9@4960,9640
JTAG_TDO: JP4.3 U2.149 | length 1657.1
  TopLayer w8: v1(4858.47,8283.53) U2.149@4937.69,8283.53
  BottomLayer w8: JP4.3@4660,9640 4660,9536 4492,9368 4492,8874 4858.47,8507.53 v1(4858.47,8283.53)
JTAG_TMS: JP4.5 R16.1 U2.148 | length 1814.2
  TopLayer w8: JP4.5@4760,9640 4826.54,9573.46 R16.1@4826.54,9500 ; v1(4878,8303.21) U2.148@4937.69,8303.21
  BottomLayer w8: JP4.5@4760,9640 4760,9583 4517,9340 4517,8888 4878,8527 v1(4878,8303.21)
LVDS1_INN: JP1.2 R43.1 U2.179 | length 1914.6
  TopLayer w8: JP1.2@4348.43,6489.57 JP1.2@4151.57,6489.57 JP1.2@4151.57,6686.43 4338,6686.43 4573,6921.43 4573,7306.46 4761,7494.46 4761,7652 4801.98,7692.98 U2.179@4937.69,7692.98
LVDS1_INP: JP1.1 R43.2 U2.180 | length 1525
  TopLayer w8: JP1.1@4250,6588 4391,6588 4437,6634 4437,6753 4592,6908 4592,7258.54 4689,7355.54 4689,7394 4781,7486 4781,7640 4814.29,7673.29 U2.180@4937.69,7673.29
LVDS2_INN: JP2.2 R42.1 U2.177 | length 1631.7
  TopLayer w8: JP2.2@4348.43,6929.57 JP2.2@4151.57,6929.57 JP2.2@4151.57,7126.43 4482.43,7126.43 4497,7141 4497,7393 4579,7475 4579,7512.46 4701,7634.46 4701,7688 4745.35,7732.35 U2.177@4937.69,7732.35
LVDS2_INP: JP2.1 R42.2 U2.178 | length 1173.4
  TopLayer w8: JP2.1@4250,7028 4419,7028 4518,7127 4518,7384.54 4684,7550.54 4684,7585 4721,7622 4721,7675 4758.66,7712.66 U2.178@4937.69,7712.66
LVDS3_INN: JP7.2 R77.1 U2.173 | length 1272.9
  TopLayer w8: JP7.2@4348.43,7389.57 JP7.2@4151.57,7389.57 JP7.2@4151.57,7586.43 4472.96,7586.43 R77.1@4640,7753.46 4674.46,7753.46 4732.09,7811.09 U2.173@4937.69,7811.09
LVDS3_INP: JP7.1 R77.2 U2.174 | length 801.7
  TopLayer w8: JP7.1@4250,7488 4401.46,7488 4620,7706.54 ; R77.2@4640,7686.54 4744.87,7791.4 U2.174@4937.69,7791.4
LVDS3_OUTN: JP10.3 R1.1 R3.1 | length 366.8
  TopLayer w8: JP10.3@4360,8700 4543.54,8700 R1.1@4590,8746.46 4670,8746.46 R3.1@4696.54,8773
LVDS3_OUTP: JP10.1 R1.2 R2.1 | length 372.2
  TopLayer w8: JP10.1@4360,8600 4439.54,8679.54 R1.2@4590,8679.54 4596.54,8673 R2.1@4696.54,8673
LVDS6_INN: JP10.4 R46.1 U2.164 | length 1102.9
  TopLayer w8: v1(4777,8157) 4813.46,8120.54 R46.1@4813.46,8100 4817,8100 4876,8041 4876,8015 4902.75,7988.25 U2.164@4937.69,7988.25
  BottomLayer w8: JP10.4@4260,8700 4301,8659 4436,8659 4492,8603 4492,8427 4762,8157 v1(4777,8157)
LVDS6_INP: JP10.2 R46.2 U2.165 | length 1130.7
  TopLayer w8: v1(4746.54,8146.46) 4746.54,8082.46 4776,8053 4839,8053 4859,8033 4859,8008 4898.43,7968.57 U2.165@4937.69,7968.57
  BottomLayer w8: JP10.2@4260,8600 4303,8643 4427,8643 4473.75,8596.25 4473.75,8419.25 v1(4746.54,8146.46)
LVDS_CLKN: JP11.2 R4.1 U2.152 | length 1302.1
  TopLayer w8: JP11.2@4338.43,8241.58 JP11.2@4141.57,8241.58 JP11.2@4141.57,8438.42 4455.04,8438.42 4559,8334.46 4559,8294 4628.53,8224.47 U2.152@4937.69,8224.47
LVDS_CLKP: JP11.1 R4.2 U2.153 | length 753.7
  TopLayer w8: JP11.1@4240,8340 4486.54,8340 4621.75,8204.79 U2.153@4937.69,8204.79
LVDS_PLLN: JP13.1 R5.1 R7.1 | length 268.4
  TopLayer w8: JP13.1@4680,8560 4600,8480 R5.1@4600,8453.46 4653.46,8400 R7.1@4706.54,8400
LVDS_PLLP: JP13.2 R5.2 R6.1 | length 345.7
  TopLayer w8: JP13.2@4580,8560 4554,8534 4554,8432.54 R5.2@4600,8386.54 4620,8386.54 R6.1@4706.54,8300
NCE: JP5.6 R28.2 U2.33 | length 952.7
  TopLayer w6: U2.33@6274.31,8303.21 v1(6328.79,8303.21) ; v1(6509,8123) 6668,7964 6668,7877 6694,7851 6769,7851 6886.54,7733.46 R28.2@6886.54,7680
  BottomLayer w6: v1(6328.79,8303.21) v1(6509,8123)
NCEO: U2.32
NetC54_2: C54.2 U15.18 | length 311.8
  TopLayer w12: C54.2@8320,9626.54 8387.54,9559 8466,9559 8511.18,9513.82 U15.18@8511.18,9439.84
NetC64_2: C64.2 U15.17 | length 226.8
  TopLayer w12: C64.2@8440,9626.54 8440,9620 8536.77,9523.23 U15.17@8536.77,9439.84
NetC102_1: C102.1 U15.5 | length 126.6
  TopLayer w12: v3(8562.36,9114.36) U15.5@8562.36,9180
  BottomLayer w12: C102.1@8546.54,9060 8546.54,9098.54 v3(8562.36,9114.36)
NetC102_2: C102.2 L1.1 U15.6 U15.7 U15.8 U15.9 U15.10 | length 47.5
  BottomLayer w12: v3(8613,9012) C102.2@8613,9059.54
NetC113_1: C113.1 C118.1 C122.1 R67.2 R70.1 U15.2 | length 911.1
  TopLayer w12: R70.1@8040,9293.46 7960,9293.46 C122.1@7933.46,9320 7975.46,9362 8191,9362 8213.46,9339.54 C113.1@8213.46,9280 R67.2@8306.54,9280 8306.54,9256.46 8373.46,9189.54 C118.1@8373.46,9160 8413.46,9120 8482,9120 8485.59,9123.59 U15.2@8485.59,9180
NetC113_2: C113.2 R68.1 | length 100
  TopLayer w12: R68.1@8146.54,9180 C113.2@8146.54,9280
NetC118_2: C118.2 R68.2 U15.3 | length 409.3
  TopLayer w12: R68.2@8213.46,9180 8233.46,9160 C118.2@8306.54,9160 8372.54,9094 8494,9094 8511.18,9111.18 U15.3@8511.18,9180
NetC122_2: C122.2 R69.1 | length 100
  TopLayer w12: R69.1@7866.54,9220 C122.2@7866.54,9320
NetC160_2: C160.2 C161.2 FB3.2 U21.4 | length 334.7
  TopLayer w12: FB3.2@8993,8896 8993.46,8570.54 U21.4@9000,8564
NetC163_2: C163.2 C164.1 U1.V6 U20.3 | length 902.6
  TopLayer w6: v1(8750,7522.44) U1.V6@8769.15,7503.29
  TopLayer w8: C164.1@8640,8202.57 C164.1@8642.57,8200 ; C163.2@8642.57,8083.97 C163.2@8646.54,8080
  TopLayer w12: U20.3@8640,8343.15 8642.57,8340.58 C164.1@8642.57,8200 8646.54,8196.03 8646.54,7972.46 v1(8729,7890)
  BottomLayer w6: v1(8729,7890) 8729,7543.44 v1(8750,7522.44)
NetDS1_2: DS1.2 R15.1 | length 149.5
  TopLayer w8: DS1.2@5004,7164.6 5004,7016.46 R15.1@5005,7015.46
NetDS2_2: DS2.2 R18.1 | length 149.5
  TopLayer w8: DS2.2@4887,7155.6 4887,7007.46 R18.1@4888,7006.46
NetDS3_2: DS3.2 R19.1 | length 149.5
  TopLayer w8: DS3.2@4766,7156.6 4766,7008.46 R19.1@4767,7007.46
NetDS6_1: DS6.1 R62.1 | length 109.1
  TopLayer w12: DS6.1@8937.4,9020 R62.1@9046.54,9020
NetDS9_1: DS9.1 R86.2 | length 96.1
  TopLayer w6: R86.2@8813.46,6580 DS9.1@8814.46,6483.94
NetJP6_1: JP6.1 R20.1 | length 106.5
  BottomLayer w8: R20.1@9245.46,8890 JP6.1@9352,8890
NetJP6_2: JP6.2 R75.2 | length 106.5
  TopLayer w8: JP6.2@9452,8890 R75.2@9558.54,8890
NetJP6_3: JP6.3 R21.1 | length 106.5
  BottomLayer w8: R21.1@9245.46,8790 JP6.3@9352,8790
NetJP6_4: JP6.4 R85.2 | length 106.5
  TopLayer w8: JP6.4@9452,8790 R85.2@9558.54,8790
NetJP6_5: JP6.5 R53.1 | length 106.5
  BottomLayer w8: R53.1@9245.46,8690 JP6.5@9352,8690
NetJP6_6: JP6.6 R89.2 | length 106.5
  TopLayer w8: JP6.6@9452,8690 R89.2@9558.54,8690
NetJP6_7: JP6.7 R60.1 | length 106.5
  BottomLayer w8: R60.1@9245.46,8590 JP6.7@9352,8590
NetJP6_8: JP6.8 R90.2 | length 106.5
  TopLayer w8: JP6.8@9452,8590 R90.2@9558.54,8590
NetJP6_9: JP6.9 R63.1 | length 106.5
  BottomLayer w8: R63.1@9245.46,8490 JP6.9@9352,8490
NetJP6_10: JP6.10 R91.2 | length 106.5
  TopLayer w8: JP6.10@9452,8490 R91.2@9558.54,8490
NetQ1_1: Q1.1 R73.1 U14.1 | length 1081.4
  TopLayer w12: U14.1@7166.54,9633.46 U14.1@7180,9620 7180,9694 7255,9769 7918,9769 7940,9747 Q1.1@7940,9709.21 7949.21,9700 R73.1@8086.54,9700
NetQ1_2: Q1.2 R72.1 | length 112.4
  TopLayer w12: Q1.2@7902.6,9610.79 7902.6,9503.94 R72.1@7906.54,9500
NetR2_2: R2.2 U2.122 | length 281.9
  TopLayer w8: R2.2@4763.46,8673 4806,8715.54 4806,8799 4822.02,8815.02 U2.122@4937.69,8815.02
NetR3_2: R3.2 U2.121 | length 208.3
  TopLayer w8: R3.2@4763.46,8773 4763.46,8787.46 4810.71,8834.71 U2.121@4937.69,8834.71
NetR6_2: R6.2 U2.144 | length 198.2
  TopLayer w8: R6.2@4773.46,8300 4855.42,8381.95 U2.144@4937.69,8381.95
NetR7_2: R7.2 U2.143 | length 164.9
  TopLayer w8: R7.2@4773.46,8400 4775.1,8401.64 U2.143@4937.69,8401.64
NetR22_2: R22.2 U2.34 | length 150.3
  TopLayer w8: v1(6181,8300) 6203.9,8322.9 U2.34@6274.31,8322.9
  BottomLayer w8: R22.2@6133.46,8300 v1(6181,8300)
NetR23_2: R23.2 U2.35 | length 177.9
  TopLayer w8: v1(6208.58,8342.58) U2.35@6274.31,8342.58
  BottomLayer w8: R23.2@6133.46,8420 6208.58,8344.88 v1(6208.58,8342.58) v1@6206,8340
NetR24_1: R24.1 U4.3 | length 213.7
  TopLayer w12: R24.1@6553.46,8220 U4.3@6767.15,8220
NetR25_1: R25.1 U6.3 | length 166.1
  TopLayer w8: R25.1@6393.46,9340 6492.85,9340 U6.3@6540,9292.85
NetR30_1: R30.1 U1.K25 | length 456.1
  TopLayer w6: R30.1@7626,7041 7673,7041 7692.45,7060.45 7790.45,7060.45 7899,7169 8001.79,7169 U1.K25@8021.12,7188.33
NetR30_2: R30.2 U1.K26 | length 401.9
  TopLayer w6: R30.2@7626,7077 7781,7077 7892.33,7188.33 U1.K26@7981.75,7188.33
NetR30_3: R30.3 U1.L25 | length 442.6
  TopLayer w6: R30.3@7626,7113 7792,7113 7887,7208 8001.42,7208 U1.L25@8021.12,7227.7
NetR30_4: R30.4 U1.L26 | length 388.3
  TopLayer w6: R30.4@7626,7149 7797,7149 7875.7,7227.7 U1.L26@7981.75,7227.7
NetR31_1: R31.1 U1.A23 | length 234
  TopLayer w6: R31.1@8066,6614 8066,6652 8099.86,6685.86 U1.A23@8099.86,6834
NetR31_2: R31.2 U1.B23 | length 288.3
  TopLayer w6: R31.2@8030,6614 8030,6650 8079,6699 8079,6852.51 U1.B23@8099.86,6873.37
NetR31_3: R31.3 U1.A24 | length 247.5
  TopLayer w6: R31.3@7994,6614 7994,6652 8060.49,6718.49 U1.A24@8060.49,6834
NetR31_4: R31.4 U1.B24 | length 301.8
  TopLayer w6: R31.4@7958,6614 7958,6647 8040,6729 8040,6852.88 U1.B24@8060.49,6873.37
NetR32_1: R32.1 U1.A20 | length 223.3
  TopLayer w6: U1.A20@8217.97,6834 8217.97,6664.03 8226,6656 R32.1@8226,6614
NetR32_2: R32.2 U1.B20 | length 271
  TopLayer w6: R32.2@8190,6614 8199,6623 8199,6854.4 U1.B20@8217.97,6873.37
NetR32_3: R32.3 U1.A21 | length 230.2
  TopLayer w6: R32.3@8154,6614 8154,6651 8178.6,6675.6 U1.A21@8178.6,6834
NetR32_4: R32.4 U1.B21 | length 284.5
  TopLayer w6: R32.4@8118,6614 8118,6650 8159,6691 8159,6853.77 U1.B21@8178.6,6873.37
NetR33_1: R33.1 U1.B22 | length 289.7
  TopLayer w6: v1(8120,6854.14) U1.B22@8139.23,6873.37
  BottomLayer w6: R33.1@8066,6614 8066,6754 8120,6808 v1(8120,6854.14)
NetR33_2: R33.2 U1.C22 | length 347.1
  TopLayer w6: U1.C22@8139.23,6912.74 v1(8158,6893.97)
  BottomLayer w6: R33.2@8102,6614 8102,6648 8179,6725 8179,6872.97 v1(8158,6893.97)
NetR33_3: R33.3 U1.C21 | length 332.5
  TopLayer w6: U1.C21@8178.6,6912.74 v1(8199,6892.34)
  BottomLayer w6: R33.3@8138,6614 8138,6644 8199,6705 v1(8199,6892.34)
NetR33_4: R33.4 U1.D21 | length 372.7
  TopLayer w6: U1.D21@8178.6,6952.11 v1(8198,6932.71)
  BottomLayer w6: R33.4@8174,6614 8174,6644 8218,6688 8218,6912.71 v1(8198,6932.71)
NetR34_1: R34.1 U1.C20 | length 312
  TopLayer w6: U1.C20@8217.97,6912.74 v1(8238,6892.71)
  BottomLayer w6: R34.1@8226,6614 8238,6626 v1(8238,6892.71)
NetR34_2: R34.2 U1.D20 | length 356.3
  TopLayer w6: U1.D20@8217.97,6952.11 v1(8238,6932.08)
  BottomLayer w6: v1(8238,6932.08) 8257,6913.08 8257,6619 R34.2@8262,6614
NetR34_3: R34.3 U1.C19 | length 315.6
  TopLayer w6: U1.C19@8257.34,6912.74 v1(8277,6893)
  BottomLayer w6: v1(8277,6893) 8277,6782 8298,6761 R34.3@8298,6614
NetR34_4: R34.4 U1.D19 | length 369.9
  TopLayer w6: U1.D19@8257.34,6952.11 v1(8277,6932.45)
  BottomLayer w6: v1(8277,6932.45) 8295,6914.45 8295,6798 8334,6759 R34.4@8334,6614
NetR35_1: R35.1 U1.H24 | length 465.8
  TopLayer w6: v1(8040.9,7090) U1.H24@8060.49,7109.59
  BottomLayer w6: R35.1@7626,7034 7716,7034 7772,7090 v1(8040.9,7090)
NetR35_2: R35.2 U1.H23 | length 520.1
  TopLayer w6: v1(8081.27,7091) U1.H23@8099.86,7109.59
  BottomLayer w6: R35.2@7626,6998 7717,6998 7790,7071 8061.27,7071 v1(8081.27,7091)
NetR35_3: R35.3 U1.G25 | length 439.9
  TopLayer w6: v1(7941,7051) 8001.9,7051 U1.G25@8021.12,7070.22
  BottomLayer w6: R35.3@7626,6962 7710,6962 7799,7051 v1(7941,7051)
NetR35_4: R35.4 U1.G24 | length 494.2
  TopLayer w6: v1(8041.27,7051) U1.G24@8060.49,7070.22
  BottomLayer w6: R35.4@7626,6926 7709,6926 7810,7027 7960,7027 7984,7051 v1(8041.27,7051)
NetR36_1: R36.1 U1.G23 | length 555.3
  TopLayer w6: v1(8079,7049) 8099.86,7069.86 U1.G23@8099.86,7070.22
  BottomLayer w6: R36.1@7626,6874 7694,6874 7828,7008 7973,7008 7996,7031 8061,7031 v1(8079,7049)
NetR36_2: R36.2 U1.F24 | length 514.4
  TopLayer w6: v1(8041.64,7012) U1.F24@8060.49,7030.85
  BottomLayer w6: R36.2@7626,6838 7689,6838 7820,6969 7971,6969 8014,7012 v1(8041.64,7012)
NetR36_3: R36.3 U1.F23 | length 568.7
  TopLayer w6: v1(8081.01,7012) U1.F23@8099.86,7030.85
  BottomLayer w6: R36.3@7626,6802 7685,6802 7833,6950 7978,6950 8021,6993 8062.01,6993 v1(8081.01,7012)
NetR36_4: R36.4 U1.E24 | length 527.9
  TopLayer w6: v1(8041.01,6972) U1.E24@8060.49,6991.48
  BottomLayer w6: R36.4@7626,6766 7685,6766 7852,6933 8002.01,6933 v1(8041.01,6972)
NetR37_1: R37.1 U1.E25 | length 440.9
  TopLayer w6: R37.1@7626,6881 7735,6881 7826,6972 8001.64,6972 U1.E25@8021.12,6991.48
NetR37_2: R37.2 U1.F25 | length 442.3
  TopLayer w6: R37.2@7626,6917 7739,6917 7811,6989 7844,6989 7867,7012 8002.27,7012 U1.F25@8021.12,7030.85
NetR37_3: R37.3 U1.F26 | length 388
  TopLayer w6: R37.3@7626,6953 7744.15,6953 7797.15,7006 7829,7006 7853.85,7030.85 U1.F26@7981.75,7030.85
NetR37_4: R37.4 U1.G26 | length 389.4
  TopLayer w6: R37.4@7626,6989 7750,6989 7782,7021 7805,7021 7854.22,7070.22 U1.G26@7981.75,7070.22
NetR38_1: R38.1 U1.C25 | length 474.5
  TopLayer w6: R38.1@7626,6721 7703,6721 7875,6893 8001.38,6893 U1.C25@8021.12,6912.74
NetR38_2: R38.2 U1.C26 | length 424.1
  TopLayer w6: R38.2@7628.74,6759.74 R38.2@7626,6757 7709,6757 7864.74,6912.74 U1.C26@7981.75,6912.74
NetR38_3: R38.3 U1.D25 | length 461
  TopLayer w6: R38.3@7626,6793 7713,6793 7852,6932 8001.01,6932 U1.D25@8021.12,6952.11
NetR38_4: R38.4 U1.D26 | length 406.7
  TopLayer w6: R38.4@7626,6829 7716,6829 7839.11,6952.11 U1.D26@7981.75,6952.11
NetR39_1: R39.1 U19.21 | length 114.2
  TopLayer w8: U19.21@8031.42,8479.92 8126.46,8479.92 R39.1@8140,8493.46
NetR40_1: R40.1 U19.30 | length 237
  TopLayer w12: R40.1@7573.46,8720 7687,8720 7714.49,8692.51 U19.30@7714.49,8607.87
NetR47_1: R47.1 U1.M23 | length 520.9
  TopLayer w6: v1(8079.93,7287) U1.M23@8099.86,7267.07
  BottomLayer w6: 7644,7354 7657,7354 7738,7273 7912,7273 7947,7308 8058.93,7308 v1(8079.93,7287)
NetR47_2: R47.2 U1.M24 | length 482.1
  TopLayer w6: v1(8040.56,7287) U1.M24@8060.49,7267.07
  BottomLayer w6: R47.2@7626,7318 7660,7318 7723,7255 7921,7255 7953,7287 v1(8040.56,7287)
NetR47_3: R47.3 U1.L23 | length 521.2
  TopLayer w6: v1(8081.56,7246) U1.L23@8099.86,7227.7
  BottomLayer w6: R47.3@7626,7282 7659,7282 7703,7238 7930,7238 7960,7268 8059.56,7268 v1(8081.56,7246)
NetR47_4: R47.4 U1.L24 | length 466.1
  TopLayer w6: v1(8040.19,7248) U1.L24@8060.49,7227.7
  BottomLayer w6: R47.4@7626,7246 7628,7248 7668,7248 7695,7221 7939,7221 7966,7248 v1(8040.19,7248)
NetR48_1: R48.1 U1.P23 | length 543.5
  TopLayer w6: v1(8080.67,7365) U1.P23@8099.86,7345.81
  BottomLayer w6: R48.1@7626,7514 7656,7514 7764.29,7405.71 7890.29,7405.71 7910,7386 8059.67,7386 v1(8080.67,7365)
NetR48_2: R48.2 U1.P24 | length 489.2
  TopLayer w6: v1(8041.3,7365) U1.P24@8060.49,7345.81
  BottomLayer w6: R48.2@7626,7478 7658,7478 7743.96,7392.04 7883.96,7392.04 7911,7365 v1(8041.3,7365)
NetR48_3: R48.3 U1.N23 | length 530.4
  TopLayer w6: v1(8081,7326) 8099.86,7307.14 U1.N23@8099.86,7306.44
  BottomLayer w6: R48.3@7626,7442 7652,7442 7747,7347 8060,7347 v1(8081,7326)
NetR48_4: R48.4 U1.N24 | length 475.7
  TopLayer w6: v1(8040.93,7326) U1.N24@8060.49,7306.44
  BottomLayer w6: R48.4@7626,7406 7643,7406 7723,7326 v1(8040.93,7326)
NetR49_1: R49.1 U1.R24 | length 460.1
  TopLayer w6: R49.1@7626,7361 7763,7361 7806,7404 8041.67,7404 U1.R24@8060.49,7385.18
NetR49_2: R49.2 U1.R23 | length 501.1
  TopLayer w6: R49.2@7626,7397 7758,7397 v1(7785,7424) ; v1(8081.04,7404) U1.R23@8099.86,7385.18
  BottomLayer w6: v1(7785,7424) 7901,7424 7921,7404 v1(8081.04,7404)
NetR49_3: R49.3 U1.T25 | length 407.7
  TopLayer w6: R49.3@7626,7433 7663,7433 7674,7444 8001.67,7444 U1.T25@8021.12,7424.55
NetR49_4: R49.4 U1.T24 | length 452.9
  TopLayer w6: R49.4@7626,7469 v1(7755,7469) ; v1(8041.04,7444) U1.T24@8060.49,7424.55
  BottomLayer w6: v1(7755,7469) 7780,7444 v1(8041.04,7444)
NetR50_1: R50.1 U1.V23 | length 544.6
  TopLayer w6: v1(8081.15,7522) U1.V23@8099.86,7503.29
  BottomLayer w6: R50.1@7626,7674 7695,7674 7825,7544 8059.15,7544 v1(8081.15,7522)
NetR50_2: R50.2 U1.V24 | length 473.3
  TopLayer w6: v1(8041.78,7522) U1.V24@8060.49,7503.29
  BottomLayer w6: R50.2@7643,7638 7696,7638 7812,7522 v1(8041.78,7522)
NetR50_3: R50.3 U1.U23 | length 531.1
  TopLayer w6: v1(8080.78,7483) U1.U23@8099.86,7463.92
  BottomLayer w6: R50.3@7626,7602 7696,7602 7793,7505 8058.78,7505 v1(8080.78,7483)
NetR50_4: R50.4 U1.U24 | length 476.8
  TopLayer w6: v1(8041.41,7483) U1.U24@8060.49,7463.92
  BottomLayer w6: R50.4@7626,7566 7701,7566 7784,7483 v1(8041.41,7483)
NetR51_1: R51.1 U1.U26 | length 384.8
  TopLayer w6: R51.1@7626,7534 7723,7534 7793.08,7463.92 U1.U26@7981.75,7463.92
NetR51_2: R51.2 U1.U25 | length 439.1
  TopLayer w6: R51.2@7626,7570 7711,7570 7798,7483 8002.04,7483 U1.U25@8021.12,7463.92
NetR51_3: R51.3 U1.V26 | length 398.3
  TopLayer w6: R51.3@7626,7606 7704,7606 7806.71,7503.29 U1.V26@7981.75,7503.29
NetR51_4: R51.4 U1.V25 | length 452.6
  TopLayer w6: R51.4@7626,7642 7698,7642 7818,7522 8002.41,7522 U1.V25@8021.12,7503.29
NetR52_1: R52.1 U1.K23 | length 504.4
  TopLayer w6: v1(8079.19,7209) U1.K23@8099.86,7188.33
  BottomLayer w6: R52.1@7626,7194 7673,7194 7682,7203 7947,7203 7972,7228 8060.19,7228 v1(8079.19,7209)
NetR52_2: R52.2 U1.K24 | length 464.2
  TopLayer w6: v1(8039.82,7209) U1.K24@8060.49,7188.33
  BottomLayer w6: R52.2@7626,7158 7677,7158 7704,7185 7968,7185 7992,7209 v1(8039.82,7209)
NetR52_3: R52.3 U1.J24 | length 462.3
  TopLayer w6: v1(8040.45,7169) U1.J24@8060.49,7148.96
  BottomLayer w6: R52.3@7626,7122 7677,7122 7724,7169 v1(8040.45,7169)
NetR52_4: R52.4 U1.J25 | length 439.4
  TopLayer w6: v1(8000.16,7128) U1.J25@8021.12,7148.96
  BottomLayer w6: R52.4@7626,7086 7679,7086 7743,7150 7939,7150 7961,7128 v1(8000.16,7128)
NetR54_1: R54.1 U1.M25 | length 422.5
  TopLayer w6: R54.1@7626,7201 7817,7201 7864,7248 8002.05,7248 U1.M25@8021.12,7267.07
NetR54_2: R54.2 U1.M26 | length 368.2
  TopLayer w6: R54.2@7626,7237 7819,7237 7849.07,7267.07 U1.M26@7981.75,7267.07
NetR54_3: R54.3 U1.N26 | length 385.8
  TopLayer w6: R54.3@7626,7273 7680,7273 7733,7326 7919,7326 7938.56,7306.44 U1.N26@7981.75,7306.44
NetR54_4: R54.4 U1.P26 | length 371
  TopLayer w6: R54.4@7626,7309 7670,7309 7706.81,7345.81 U1.P26@7981.75,7345.81
NetR55_1: R55.1 U1.J26 | length 691.3
  TopLayer w6: R55.1@7379.46,6934 7452.46,7007 7671,7007 7706,7042 7796,7042 7902.96,7148.96 U1.J26@7981.75,7148.96
NetR56_2: R56.2 S1.1 | length 154.8
  BottomLayer w8: S1.1@4935,6378 4935,6251.46 R56.2@4955,6231.46
NetR57_2: R57.2 S1.2 | length 146.5
  BottomLayer w8: R57.2@4835,6231.46 S1.2@4835,6378
NetR65_2: R65.2 U15.20 | length 167.6
  TopLayer w12: R65.2@8360,9453.46 8403.54,9497 8447,9497 8460,9484 U15.20@8460,9439.84
NetR66_1: R66.1 U15.19 | length 329.9
  TopLayer w12: R66.1@8260,9453.46 8335.54,9529 8458,9529 8485.59,9501.41 U15.19@8485.59,9439.84
NetR76_1: R76.1 U23.3 | length 253.7
  TopLayer w8: R76.1@8460,8113.46 U23.3@8460,8367.15
NetR79_2: R79.2 U1.B4 | length 550.9
  TopLayer w6: U1.B4@8847.89,6873.37 8868,6853.26 8868,6818 8850,6800 8850,6700 8862,6688 9025,6688 9051,6662 9051,6595.54 R79.2@9106.54,6540
NetR80_1: R80.1 U1.AE4 | length 337
  TopLayer w6: v1(8828,8081.46) 8828,7798.77 U1.AE4@8847.89,7778.88
  BottomLayer w6: v1(8828,8081.46) R80.1@8846.54,8100
NetR81_1: R81.1 U18.4 | length 347.2
  TopLayer w6: U18.4@7225.2,7841.89 7225.2,7891.8 7184,7933 7184,8082 7202,8100 R81.1@7266.54,8100
NetR81_2: R81.2 R83.2 U1.C5 | length 4540.4
  TopLayer w6: R81.2@7333.46,8100 7345.46,8088 7503,8088 7642,8227 7794,8227 v1(7813,8246) ; U1.C5@8808.52,6912.74 8788,6892.22 8788,6678.54 8987.54,6479 9217,6479 9260,6522 v2(9260,6703)
  BottomLayer w6: v1(7813,8246) 7964,8246 8024,8186 8568,8186 8709,8045 9293,8045 9384,7954 9384,7729 9366,7711 9366,6809 v2(9260,6703)
NetR82_1: R82.1 U21.3 | length 213.7
  TopLayer w8: R82.1@9000,8153.46 U21.3@9000,8367.15
NetR84_2: R84.2 U1.B5 | length 320.6
  TopLayer w6: U1.B5@8808.52,6873.37 8828,6853.89 8828,6679 8867,6640 R84.2@8926.54,6640 R84.2@8926.54,6643.46
NetS2_2: S2.2 U18.3 | length 760.2
  TopLayer w12: U18.3@7225.2,7960 v1(7225.2,8027.2)
  BottomLayer w12: S2.2@7170,8697.32 7225.2,8642.13 v1(7225.2,8027.2)
NSTATUS: R29.1 U2.146 | length 139.9
  TopLayer w12: U2.146@4937.69,8342.58 4990.42,8342.58 v3(5005,8328)
  BottomLayer w12: v3(5005,8328) 5054.54,8328 R29.1@5066.54,8340
OUT1+: C3.1 U3.B9 | length 1687.8
  TopLayer w8: C3.1@4553.46,9380 4584.46,9411 5123,9411 5390,9678 5927,9678 5971,9634 5971,9533.59 U3.B9@5990.96,9513.63
OUT1-: C4.1 U3.A9 | length 1675
  TopLayer w8: C4.1@4553.46,9480 4599.17,9434.3 5116.3,9434.3 5378,9696 5935,9696 5990.96,9640.04 U3.A9@5990.96,9553
OUT2+: U3.A4
OUT2-: U3.B4 | length 28.1
  TopLayer w6: U3.B4@5794.11,9513.63 5814,9533.52
P\C\I\6\6\: R74.1 U1.AD1 | length 577
  TopLayer w6: v1(8947,7758.51) U1.AD1@8966,7739.51 ; v1(8947,7978) v1(8947,8166.46)
  BottomLayer w6: R74.1@8913.46,8200 v1(8947,8166.46) ; v1(8947,7758.51) 8905.49,7758.51 8861.99,7802.01 8861.99,7892.99 v1(8947,7978)
P_AD0: U1.Y3 U9.29 | length 320.8
  TopLayer w6: U1.Y3@8887.26,7582.03 v1(8908,7562)
  BottomLayer w6: v1(8908,7562) 9053.99,7562 9090,7525.98 U9.29@9185.04,7525.98
P_AD1: U1.AA1 U9.35 | length 228.4
  TopLayer w6: U1.AA1@8966,7621.4 9008.4,7621.4 v1(9031.09,7644.1)
  BottomLayer w6: v1(9031.09,7644.1) U9.35@9185.04,7644.1
P_AD2: U1.Y4 U9.28 | length 368.5
  TopLayer w6: U1.Y4@8847.89,7582.03 v1(8867.92,7562)
  BottomLayer w6: v1(8867.92,7562) 8885.92,7544 9046,7544 9083.7,7506.3 U9.28@9185.04,7506.3
P_AD3: U1.Y2 U9.34 | length 276
  TopLayer w6: U1.Y2@8926.63,7582.03 8945.6,7601 9037,7601 v1(9060.41,7624.41)
  BottomLayer w6: v1(9060.41,7624.41) U9.34@9185.04,7624.41
P_AD4: U1.W3 U9.27 | length 321
  TopLayer w6: U1.W3@8887.26,7542.66 v1(8905.92,7524)
  BottomLayer w6: v1(8905.92,7524) 9039,7524 9076.39,7486.61 U9.27@9185.04,7486.61
P_AD5: U1.Y1 U9.33 | length 228.4
  TopLayer w6: U1.Y1@8966,7582.03 9047.03,7582.03 9069.73,7604.73 v1(9128.73,7604.73)
  BottomLayer w6: v1(9128.73,7604.73) U9.33@9185.04,7604.73
P_AD6: U1.W4 U9.26 | length 368.5
  TopLayer w6: U1.W4@8847.89,7542.66 v1(8866.55,7524)
  BottomLayer w6: v1(8866.55,7524) 8886.55,7504 9032,7504 9069.07,7466.93 U9.26@9185.04,7466.93
P_AD7: U1.W2 U9.31 | length 288.2
  TopLayer w6: U1.W2@8926.63,7542.66 8946.97,7563 9057,7563 v1(9080,7586)
  BottomLayer w6: v1(9080,7586) 9100,7586 9120.65,7565.35 U9.31@9185.04,7565.35 U9.31@9182.68,7563
P_AD8: U1.V2 U9.30 | length 276
  TopLayer w6: U1.V2@8926.63,7503.29 8947.34,7524 9109,7524 v1(9130.67,7545.67)
  BottomLayer w6: v1(9130.67,7545.67) U9.30@9185.04,7545.67
P_AD9: U1.V3 U9.25 | length 321
  TopLayer w6: U1.V3@8887.26,7503.29 v1(8906.55,7484)
  BottomLayer w6: v1(8906.55,7484) 9032,7484 9068.75,7447.24 U9.25@9185.04,7447.24
P_AD10: U1.V1 U11.25 | length 273.1
  TopLayer w6: U1.V1@8966,7503.29 9010.71,7503.29 9141.25,7372.76 U11.25@9185.04,7372.76
P_AD11: U1.U4 U10.44 | length 396.2
  TopLayer w6: U1.U4@8847.89,7463.92 v1(8867.81,7444)
  BottomLayer w6: v1(8867.81,7444) 8885.81,7426 8960,7426 8981,7405 9029,7405 9112.74,7321.26 U10.44@9185.04,7321.26
P_AD12: U1.U2 U11.26 | length 321
  TopLayer w6: U1.U2@8926.63,7463.92 8946.71,7484 9006,7484 9136.93,7353.07 U11.26@9185.04,7353.07
P_AD13: U1.U3 U10.45 | length 348.7
  TopLayer w6: U1.U3@8887.26,7463.92 v1(8907.18,7444)
  BottomLayer w6: v1(8907.18,7444) 9018,7444 9121.06,7340.94 U10.45@9185.04,7340.94
P_AD14: U1.U1 U11.27 | length 273.1
  TopLayer w6: U1.U1@8966,7463.92 9003.08,7463.92 9133.61,7333.39 U11.27@9185.04,7333.39
P_AD15: U1.T3 U10.43 | length 348.7
  TopLayer w6: U1.T3@8887.26,7424.55 v1(8905.81,7406)
  BottomLayer w6: v1(8905.81,7406) 8958,7406 8977.45,7386.55 9025.45,7386.55 9110.42,7301.57 U10.43@9185.04,7301.57
P_AD16: U1.M3 U10.37 | length 352.3
  TopLayer w6: U1.M3@8887.26,7267.07 v1(8907.33,7247)
  BottomLayer w6: v1(8907.33,7247) 8972,7247 8996,7271 9012,7271 9099.53,7183.47 U10.37@9185.04,7183.47
P_AD17: U1.M2 U11.34 | length 304.5
  TopLayer w6: U1.M2@8926.63,7267.07 8946.56,7287 9042,7287 9133.41,7195.59 U11.34@9185.04,7195.59
P_AD18: U1.M4 U10.36 | length 395.7
  TopLayer w6: U1.M4@8847.89,7267.07 v1(8867.96,7247)
  BottomLayer w6: v1(8867.96,7247) 8885.96,7229 8974,7229 8993,7248 9014,7248 9098.22,7163.78 U10.36@9185.04,7163.78
P_AD19: U1.L2 U11.36 | length 304
  TopLayer w6: U1.L2@8926.63,7227.7 8945.93,7247 9033,7247 9123.78,7156.22 U11.36@9185.04,7156.22
P_AD20: U1.L3 U10.35 | length 332.4
  TopLayer w6: U1.L3@8887.26,7227.7 v1(8905.96,7209)
  BottomLayer w6: v1(8905.96,7209) 9030,7209 9094.91,7144.1 U10.35@9185.04,7144.1
P_AD21: U1.K2 U11.37 | length 297
  TopLayer w6: U1.K2@8926.63,7188.33 8947.3,7209 9045,7209 9117.47,7136.53 U11.37@9185.04,7136.53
